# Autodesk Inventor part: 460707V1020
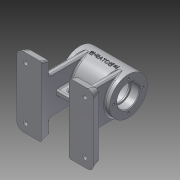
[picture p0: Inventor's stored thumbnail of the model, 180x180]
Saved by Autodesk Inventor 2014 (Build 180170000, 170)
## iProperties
Created: 2016-07
Part Number: 460707V1020
Material: 알루미늄 6061
Document SubType Name: Modeling
Designer: USER
Density: 2.71 g/cm^3
Appearance: 알루미늄 - 평지
Mass: 499.058 g
Surface Area: 540.429 cm^2
Volume: 184.154 cm^3
Author: USER
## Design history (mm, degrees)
sketch "스케치1"
  geometry: C1 r 27 at (0, 0); 1 further point
  constraints: 1 centre point, 1 coincident
  dimensions: "d0" = 54 diameter of C1
extrude "돌출1" new body sketch "스케치1" distance "d1" = 70; taper "d2" = 0 deg
sketch "스케치2"
  geometry: C1 r 27 at (0, 0) reference; C2 r 16 at (0, 0)
  constraints: 1 centre point, 1 coincident
  dimensions: "d3" = 32 diameter of C2
extrude "돌출2" cut sketch "스케치2" distance "d4" = 12; taper "d5" = 0 deg
sketch "스케치3"
  geometry: C1 r 16 at (0, 0) reference; C2 r 14 at (0, 0)
  constraints: 1 centre point, 1 coincident
  dimensions: "d6" = 28 diameter of C2
extrude "돌출3" cut sketch "스케치3" distance "d7" = 2; taper "d8" = 0 deg
sketch "스케치4"
  geometry: C1 r 14 at (0, 0) reference; C2 r 22 at (0, 0)
  constraints: 1 centre point, 1 coincident
  dimensions: "d9" = 44 diameter of C2
extrude "돌출4" cut sketch "스케치4" distance "d10" = 42; taper "d11" = 0 deg
sketch "스케치5"
  geometry: C1 r 27 at (0, 0) reference; C2 r 16 at (0, 0)
  constraints: 1 centre point, 1 coincident
  dimensions: "d12" = 32 diameter of C2
extrude "돌출5" cut sketch "스케치5" distance "d13" = 12; taper "d14" = 0 deg
sketch "스케치6"
  geometry: C1 r 16 at (0, 0) reference; C2 r 14 at (0, 0)
  constraints: 1 centre point, 1 coincident
  dimensions: "d15" = 28 diameter of C2
extrude "돌출6" cut sketch "스케치6" distance "d16" = 12; taper "d17" = 0 deg
sketch "스케치7"
  geometry: C1 r 16 at (0, 0) reference; 1 further point
  constraints: 1 vertical alignment
  dimensions: "d18" = 21 distance of C1.centre point (0, 21)
hole "구멍1" sketch "스케치7" at (0, 21) diameter "d19" = 3.242; stored, may be unused: countersink angle "d23" = 90 deg, drill point angle "d25" = 118 deg; dims "d20" = 8, "d21" = 4, "d22" = 2, "d24" = 10
node "작업 평면1"
node "작업 평면2"
sketch "스케치8"
  geometry: C1 r 5 at (-22, 0); 1 further point
  constraints: 1 centre point, 1 horizontal alignment
  dimensions: "d30" = 10 diameter of C1; "d31" = 22 distance of point (0, 0) C1.centre
extrude "돌출7" join sketch "스케치8" stored distance "d32" = 12; taper "d33" = 0 deg
sketch "스케치9"
  geometry: C1 r 5 at (0, 0) reference; 2 further points
  constraints: 1 coincident
hole "구멍2" sketch "스케치9" at (0, 0) diameter "d34" = 5.188; stored, may be unused: countersink angle "d38" = 90 deg, drill point angle "d40" = 118 deg; dims "d35" = 8, "d36" = 4, "d37" = 2, "d39" = 10
chamfer "모따기1" distance "d42" = 1; stored, may be unused: second distance "d43" = 2, angle "d44" = 45 deg
fillet "모깎기2" dims "d45" = 2
node "작업 평면3"
fillet "모깎기1" dims "d41" = 3
sketch "스케치10"
  geometry: L1 (20, 50)-(-90, 50); L2 (-90, 50)-(-90, -50); L3 (-90, -50)-(20, -50); L4 (20, -50)-(20, 50); L5 (-70, 27)-(-70, -27) reference; L6 (0, -27)-(0, 27) reference; L7 (0, 27)-(-70, 27) reference; 5 further points
  constraints: 8 end point, 3 midpoint, 2 parallel, 1 horizontal, 1 horizontal alignment, 1 perpendicular, 1 vertical alignment, 1 other
  dimensions: "d47" = 110 distance of L3.end L2.end; "d48" = 100 distance of L2.end L1.end
extrude "돌출8" join sketch "스케치10" distance "d49" = 12; taper "d50" = 0 deg
sketch "스케치11"
  geometry: L1 (-20, 50)-(90, 50) reference; L2 (-20, -50)-(-20, 50) reference; L3 (90, -50)-(-20, -50) reference; L4 (90, 50)-(90, -50) reference; L5 (15, 50)-(55, 50); L6 (55, 50)-(55, -50); L7 (55, -50)-(15, -50); L8 (15, -50)-(15, 50); 2 further points
  constraints: 8 end point, 3 point on line, 2 parallel, 1 horizontal, 1 perpendicular
  dimensions: "d51" = 35 distance from line of L5.start L2; "d52" = 35 distance from line of point (55, 50) L4; "d53" = 40 distance between parallel lines of L6 L8
sketch "스케치12"
  geometry: L1 (0, 0)-(110, 0) reference; L2 (110, 0)-(110, 12) reference; L3 (0, 12)-(110, 12) reference; L4 (0, 0)-(7.126, 19.578); L5 (7.126, 19.578)-(0, 19.578); L6 (0, 19.578)-(0, 0); L7 (110, 0)-(103.471, 17.938); L8 (103.471, 17.938)-(110, 17.938); L9 (110, 17.938)-(110, 0); 1 further point
  constraints: 12 end point, 2 parallel, 1 collinear, 1 perpendicular
  dimensions: "d54" = 20 deg angle of L9 L7; "d55" = 17.93768 distance between parallel lines of L1 L8; "d56" = 20 deg angle of L4 L6; "d57" = 19.5778 distance between parallel lines of L1 L5
extrude "돌출9" cut sketch "스케치12" stored distance "d58" = 12; taper "d59" = 0 deg
extrude "돌출10" cut sketch "스케치11" distance "d60" = 12; taper "d61" = 0 deg
sketch "스케치13"
  geometry: L1 (50, -70)-(-50, -70) reference; L2 (50, -58)-(50, -70) reference; L3 (-50, -58)-(50, -58) reference; L4 (-50, -70)-(-50, -58) reference; L5 (-50, -70)-(-50, -42.584); L6 (-50, -42.584)-(-40.021, -42.584); L7 (-40.021, -42.584)-(-50, -70); L8 (50, -70)-(50, -41.761); L9 (50, -41.761)-(39.722, -41.761); L10 (39.722, -41.761)-(50, -70); 1 further point
  constraints: 12 end point, 2 perpendicular, 1 collinear, 1 point on line
  dimensions: "d62" = 20 deg angle of L7 L5; "d63" = 27.41589 distance between parallel lines of L1 L6; "d64" = 20 deg angle of L8 L10; "d65" = 28.23902 distance between parallel lines of L1 L9
extrude "돌출11" cut sketch "스케치13" stored distance "d66" = 120; taper "d67" = 0 deg
node "작업 평면4"
sketch "스케치14"
  geometry: L1 (77, 70)-(77, 6.767); L2 (23, 70)-(23, 6.767); L3 (77, 6.767)-(23, 6.767); L4 (100, 0)-(0, 0) reference; A1 r 27 centre (50, 70) between (77, 70) and (23, 70) reference; A2 r 27 centre (50, 70) between (23, 70) and (77, 70); 1 further point
  constraints: 6 end point, 4 point on circle, 2 tangent, 1 centre point, 1 coincident, 1 concentric, 1 parallel, 1 perpendicular, 1 vertical
  dimensions: "d69" = 6.7668 distance between parallel lines of L4 L3
extrude "돌출12" join sketch "스케치14" distance "d70" = 8; taper "d71" = 0 deg
sketch "스케치15"
  geometry: L1 (-20, 50)-(-20, -50) reference; L2 (55, -50)-(15, -50) reference; L3 (15, 50)-(55, 50) reference; 7 further points
  dimensions: "d72" = 12.5 distance from line of point (-7.5, -37.5) L1; "d73" = 12.5 distance from line of point (-7.5, -37.5) L2; "d74" = 12.5 distance from line of L1 point (-7.5, 37.5); "d75" = 12.5 distance from line of point (-7.5, 37.5) L3
hole "구멍3" sketch "스케치15" at (-7.5, -37.5), (-7.5, 37.5) diameter "d76" = 6; stored, may be unused: countersink angle "d80" = 90 deg, drill point angle "d82" = 118 deg; dims "d77" = 8, "d78" = 10, "d79" = 4, "d81" = 12
sketch "스케치17"
  geometry: L1 (-4, -48)-(4, -48); L2 (-4, -48)-(-4, -25); L3 (4, -48)-(4, -25); L4 (-4, -25)-(4, -25); A1 r 27 centre (0, 0) between (-27, 0) and (27, 0) reference; 3 further points
  constraints: 8 end point, 2 perpendicular, 1 horizontal, 1 midpoint, 1 parallel, 1 point on circle, 1 vertical alignment
  dimensions: "d87" = 8 distance of L1.start L1.end; "d89" = 23 distance between parallel lines of L1 L4; "d90" = 21 distance of point (0, -48) point (0, -27)
extrude "돌출13" join sketch "스케치17" stored distance "d91" = 43; taper "d92" = 0 deg
sketch "스케치18"
  geometry: L1 (40, -21.298)-(0, -21.298) reference; L2 (12, -11.298)-(28, -11.298); L3 (12, -14.798)-(28, -14.798); L4 (28, -7.798)-(12, -7.798); L5 (40, -43.298)-(0, -43.298) reference; A1 r 3.5 centre (12, -11.298) between (12, -7.798) and (12, -14.798); A2 r 3.5 centre (28, -11.298) between (28, -14.798) and (28, -7.798); 4 further points
  constraints: 8 end point, 4 point on circle, 4 tangent, 2 centre point, 2 midpoint, 2 parallel, 1 vertical alignment
  dimensions: "d93" = 7 diameter of A2; "d94" = 23 dimension on A2 A1; "d95" = 32 distance from line of L5 point (20, -11.298)
extrude "돌출14" cut sketch "스케치18" distance "d96" = 43; taper "d97" = 0 deg
sketch "스케치20"
  geometry: L1 (0, 0)-(-15.898, -25.441); L2 (0, 0)-(0, -27.58); L3 (-15.898, -25.441)-(-20.986, -22.262); L4 (-20.986, -22.262)-(-18.336, -18.022); L5 (-18.336, -18.022)-(-13.248, -21.201)
  constraints: 10 end point, 3 perpendicular, 1 point on line, 1 vertical
  dimensions: "d109" = 30 distance of L1.start L1.end; "d110" = 32 deg angle of L2 L1; "d111" = 12 diameter of L4 L1; "d112" = 5 distance between parallel lines of L3 L5
revolve "회전1" sketch "스케치20" stored, may be unused: angle "d113" = 90 deg
sketch "스케치21"
  geometry: C1 r 6 at (0, 0) reference; 2 further points
  constraints: 1 coincident
hole "구멍4" sketch "스케치21" at (0, 0) diameter "d114" = 5.188; stored, may be unused: countersink angle "d118" = 90 deg, drill point angle "d120" = 118 deg; dims "d115" = 8, "d116" = 10, "d117" = 4, "d119" = 12
fillet "모깎기3" dims "d121" = 2
fillet "모깎기4" dims "d122" = 2
fillet "모깎기7" dims "d125" = 2
node "작업 평면5"
sketch "스케치22"
  geometry: L1 (0, 27)-(0, -27) reference; 3 further points
  constraints: 1 horizontal alignment, 1 midpoint, 1 other
  dimensions: "d127" = 35 distance from line of point (35, 0) L1
feature "엠보싱1" sketch "스케치22" dims "d128" = 0.5, "d129" = 0
fillet "모깎기12" dims "d134" = 2
fillet "모깎기13" dims "d135" = 5, "d136" = 10
fillet "모깎기14" dims "d137" = 5, "d138" = 10
fillet "모깎기15" dims "d139" = 5, "d140" = 10
fillet "모깎기16" dims "d141" = 5, "d142" = 10
fillet "모깎기17" dims "d143" = 2
fillet "모깎기18" dims "d144" = 0.3
node "솔리드1"
pattern_circular "원형 패턴1" dims angle "d27" = 360 deg
mirror "대칭1"
mirror "대칭2"
mirror "대칭3"
node "투영된 루프1"
node "투영된 루프2"
other parameters: "d68" = -8, "d126" = 27
